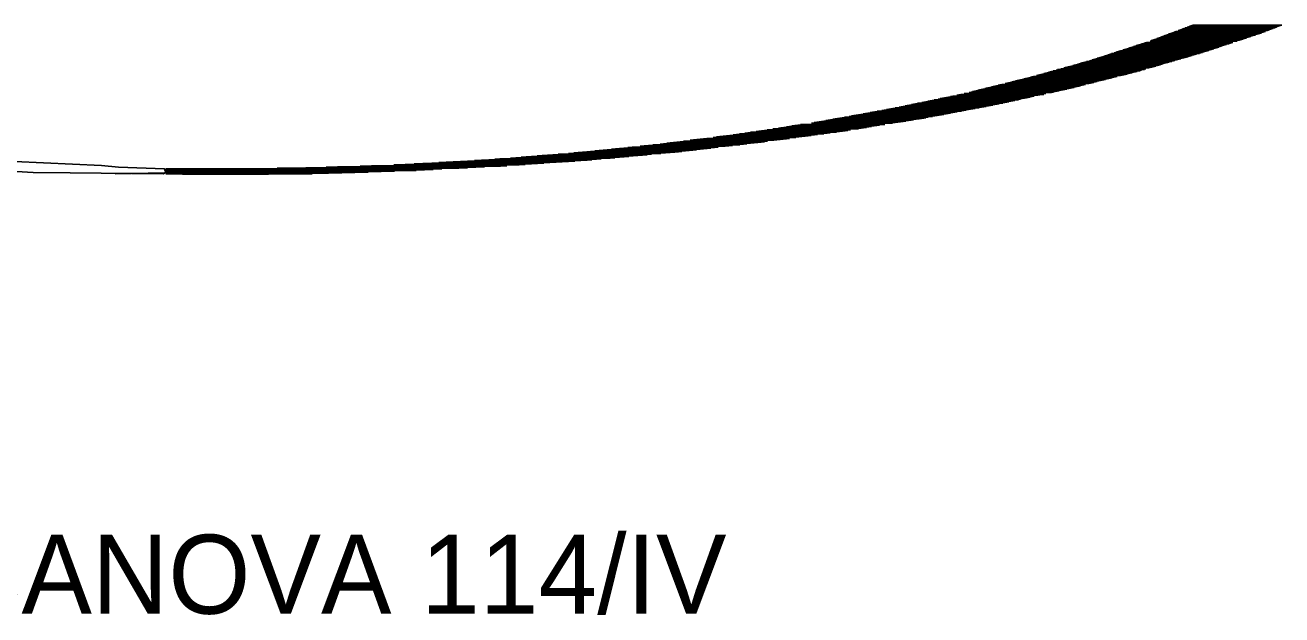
# Model space of a CAD drawing. Extents: x -5481 to -5365, y -3322 to -3178.
# Drawn here: x -5369.567 to -5367.183, y -3315.957 to -3314.837 of the extents above; entities that cross this region are included whole.
import ezdxf

# ---------------------------------------------------------------- set-up
doc = ezdxf.new("R2010")
doc.units = 0
doc.layers.add('Nová vrstva (0)', color=7, linetype='Continuous')

msp = doc.modelspace()

# ---------------------------------------------------------------- linework, layer by layer
at = {"layer": 'Nová vrstva (0)'}
for p, q in [((-5367.3853, -3314.8501), (-5367.2158, -3314.8501)), ((-5367.3834, -3314.8493), (-5367.2138, -3314.8493)), ((-5367.3792, -3314.8479), (-5367.2095, -3314.8479)), ((-5367.377, -3314.8468), (-5367.2079, -3314.8468)), ((-5367.375, -3314.8464), (-5367.2057, -3314.8464)), ((-5367.3726, -3314.8454), (-5367.2035, -3314.8454)), ((-5367.3706, -3314.8446), (-5367.2016, -3314.8446)), ((-5367.3685, -3314.844), (-5367.1992, -3314.844)), ((-5367.3662, -3314.8427), (-5367.1971, -3314.8427)), ((-5367.3642, -3314.8423), (-5367.195, -3314.8423)), ((-5367.3619, -3314.8412), (-5367.193, -3314.8412)), ((-5367.3599, -3314.8407), (-5367.1912, -3314.8407)), ((-5367.3578, -3314.8396), (-5367.189, -3314.8396)), ((-5367.3555, -3314.8388), (-5367.187, -3314.8388)), ((-5367.3535, -3314.8381), (-5367.1848, -3314.8381)), ((-5367.3512, -3314.8374), (-5367.1825, -3314.8374)), ((-5367.4491, -3314.8732), (-5367.2851, -3314.8732)), ((-5367.4467, -3314.8728), (-5367.2825, -3314.8728)), ((-5367.4444, -3314.8718), (-5367.2802, -3314.8718)), ((-5367.4419, -3314.8709), (-5367.2779, -3314.8709)), ((-5367.4395, -3314.8703), (-5367.2754, -3314.8703)), ((-5367.4326, -3314.8679), (-5367.2682, -3314.8679)), ((-5367.4304, -3314.8668), (-5367.2658, -3314.8668)), ((-5367.4282, -3314.8662), (-5367.2632, -3314.8662)), ((-5367.4262, -3314.8651), (-5367.2609, -3314.8651)), ((-5367.4241, -3314.8645), (-5367.2584, -3314.8645)), ((-5367.4219, -3314.864), (-5367.2561, -3314.864)), ((-5367.4198, -3314.8629), (-5367.2537, -3314.8629)), ((-5367.4176, -3314.862), (-5367.2511, -3314.862)), ((-5367.4154, -3314.8615), (-5367.2487, -3314.8615)), ((-5367.4131, -3314.8603), (-5367.2462, -3314.8603)), ((-5367.4111, -3314.8598), (-5367.2439, -3314.8598)), ((-5367.4089, -3314.8588), (-5367.2416, -3314.8588)), ((-5367.4067, -3314.8579), (-5367.239, -3314.8579)), ((-5367.4046, -3314.8574), (-5367.2367, -3314.8574)), ((-5367.4023, -3314.8564), (-5367.2341, -3314.8564)), ((-5367.4004, -3314.8557), (-5367.2317, -3314.8557)), ((-5367.3982, -3314.8549), (-5367.2293, -3314.8549)), ((-5367.3962, -3314.8542), (-5367.2269, -3314.8542)), ((-5367.3941, -3314.8535), (-5367.2246, -3314.8535)), ((-5367.3918, -3314.8525), (-5367.2223, -3314.8525)), ((-5367.3899, -3314.8518), (-5367.2203, -3314.8518)), ((-5367.3877, -3314.851), (-5367.2181, -3314.851)), ((-5367.5228, -3314.8975), (-5367.3606, -3314.8975)), ((-5367.5205, -3314.8965), (-5367.358, -3314.8965)), ((-5367.5176, -3314.8957), (-5367.3551, -3314.8957)), ((-5367.5153, -3314.895), (-5367.3525, -3314.895)), ((-5367.5129, -3314.894), (-5367.3496, -3314.894)), ((-5367.5105, -3314.8933), (-5367.347, -3314.8933)), ((-5367.5082, -3314.8926), (-5367.3443, -3314.8926)), ((-5367.5057, -3314.8915), (-5367.3416, -3314.8915)), ((-5367.5031, -3314.8911), (-5367.3386, -3314.8911)), ((-5367.5006, -3314.8898), (-5367.336, -3314.8898)), ((-5367.4983, -3314.8896), (-5367.3333, -3314.8896)), ((-5367.496, -3314.8884), (-5367.3308, -3314.8884)), ((-5367.4933, -3314.8876), (-5367.3284, -3314.8876)), ((-5367.491, -3314.887), (-5367.3261, -3314.887)), ((-5367.4887, -3314.8859), (-5367.3237, -3314.8859)), ((-5367.4858, -3314.8854), (-5367.3213, -3314.8854)), ((-5367.4834, -3314.8845), (-5367.3188, -3314.8845)), ((-5367.4812, -3314.8835), (-5367.3163, -3314.8835)), ((-5367.4786, -3314.8831), (-5367.3139, -3314.8831)), ((-5367.4763, -3314.8823), (-5367.3114, -3314.8823)), ((-5367.4738, -3314.8811), (-5367.3091, -3314.8811)), ((-5367.4715, -3314.8806), (-5367.3068, -3314.8806)), ((-5367.4689, -3314.8796), (-5367.3043, -3314.8796)), ((-5367.4664, -3314.8792), (-5367.3021, -3314.8792)), ((-5367.4641, -3314.8781), (-5367.2994, -3314.8781)), ((-5367.4615, -3314.8771), (-5367.2969, -3314.8771)), ((-5367.4591, -3314.8764), (-5367.2946, -3314.8764)), ((-5367.4567, -3314.8757), (-5367.2924, -3314.8757)), ((-5367.4541, -3314.8748), (-5367.2899, -3314.8748)), ((-5367.4516, -3314.8742), (-5367.2876, -3314.8742)), ((-5367.6053, -3314.9214), (-5367.4434, -3314.9214)), ((-5367.6021, -3314.9204), (-5367.4407, -3314.9204)), ((-5367.5963, -3314.9187), (-5367.4349, -3314.9187)), ((-5367.5936, -3314.9179), (-5367.4322, -3314.9179)), ((-5367.5907, -3314.9172), (-5367.4295, -3314.9172)), ((-5367.5879, -3314.9165), (-5367.4267, -3314.9165)), ((-5367.5847, -3314.9158), (-5367.4241, -3314.9158)), ((-5367.582, -3314.915), (-5367.4214, -3314.915)), ((-5367.5791, -3314.9139), (-5367.4185, -3314.9139)), ((-5367.5764, -3314.9131), (-5367.4157, -3314.9131)), ((-5367.5736, -3314.9126), (-5367.4131, -3314.9126)), ((-5367.5704, -3314.9117), (-5367.4104, -3314.9117)), ((-5367.5674, -3314.9109), (-5367.4075, -3314.9109)), ((-5367.5647, -3314.9098), (-5367.405, -3314.9098)), ((-5367.5618, -3314.9092), (-5367.4019, -3314.9092)), ((-5367.559, -3314.9084), (-5367.3992, -3314.9084)), ((-5367.5562, -3314.9078), (-5367.3964, -3314.9078)), ((-5367.5531, -3314.9067), (-5367.3937, -3314.9067)), ((-5367.5504, -3314.9062), (-5367.391, -3314.9062)), ((-5367.5475, -3314.905), (-5367.3883, -3314.905)), ((-5367.5448, -3314.9048), (-5367.3853, -3314.9048)), ((-5367.5424, -3314.9036), (-5367.3827, -3314.9036)), ((-5367.54, -3314.9028), (-5367.38, -3314.9028)), ((-5367.5375, -3314.902), (-5367.3774, -3314.902)), ((-5367.5351, -3314.9011), (-5367.3745, -3314.9011)), ((-5367.5327, -3314.9004), (-5367.372, -3314.9004)), ((-5367.5301, -3314.8996), (-5367.3688, -3314.8996)), ((-5367.5278, -3314.8989), (-5367.366, -3314.8989)), ((-5367.5252, -3314.8981), (-5367.3633, -3314.8981)), ((-5367.6947, -3314.9453), (-5367.536, -3314.9453)), ((-5367.6917, -3314.9444), (-5367.5328, -3314.9444)), ((-5367.6881, -3314.9433), (-5367.5299, -3314.9433)), ((-5367.6849, -3314.9428), (-5367.5267, -3314.9428)), ((-5367.6816, -3314.9419), (-5367.5236, -3314.9419)), ((-5367.6784, -3314.9411), (-5367.5205, -3314.9411)), ((-5367.6753, -3314.9404), (-5367.5172, -3314.9404)), ((-5367.6721, -3314.9394), (-5367.5142, -3314.9394)), ((-5367.6688, -3314.9387), (-5367.511, -3314.9387)), ((-5367.6655, -3314.938), (-5367.5079, -3314.938)), ((-5367.6628, -3314.9372), (-5367.5048, -3314.9372)), ((-5367.6598, -3314.9365), (-5367.5013, -3314.9365)), ((-5367.6572, -3314.9358), (-5367.4983, -3314.9358)), ((-5367.654, -3314.9348), (-5367.4951, -3314.9348)), ((-5367.6481, -3314.9333), (-5367.4889, -3314.9333)), ((-5367.6454, -3314.9322), (-5367.4856, -3314.9322)), ((-5367.6425, -3314.9317), (-5367.4825, -3314.9317)), ((-5367.6398, -3314.9309), (-5367.4795, -3314.9309)), ((-5367.6368, -3314.9302), (-5367.4763, -3314.9302)), ((-5367.6339, -3314.9292), (-5367.4733, -3314.9292)), ((-5367.631, -3314.9284), (-5367.4701, -3314.9284)), ((-5367.6281, -3314.9278), (-5367.4667, -3314.9278)), ((-5367.6252, -3314.9267), (-5367.4638, -3314.9267)), ((-5367.6224, -3314.9258), (-5367.4604, -3314.9258)), ((-5367.6194, -3314.9253), (-5367.4574, -3314.9253)), ((-5367.6166, -3314.9243), (-5367.4544, -3314.9243)), ((-5367.6136, -3314.9239), (-5367.4516, -3314.9239)), ((-5367.6109, -3314.9228), (-5367.4489, -3314.9228)), ((-5367.6081, -3314.9219), (-5367.446, -3314.9219)), ((-5367.7919, -3314.9692), (-5367.6383, -3314.9692)), ((-5367.7887, -3314.9688), (-5367.6344, -3314.9688)), ((-5367.7853, -3314.9675), (-5367.6307, -3314.9675)), ((-5367.7756, -3314.965), (-5367.6196, -3314.965)), ((-5367.7724, -3314.9644), (-5367.6159, -3314.9644)), ((-5367.7693, -3314.9636), (-5367.6124, -3314.9636)), ((-5367.7659, -3314.9627), (-5367.6088, -3314.9627)), ((-5367.7627, -3314.9622), (-5367.6053, -3314.9622)), ((-5367.7596, -3314.9611), (-5367.6014, -3314.9611)), ((-5367.7562, -3314.9602), (-5367.5977, -3314.9602)), ((-5367.7528, -3314.9595), (-5367.5943, -3314.9595)), ((-5367.7497, -3314.9588), (-5367.5906, -3314.9588)), ((-5367.7464, -3314.9578), (-5367.5869, -3314.9578)), ((-5367.7434, -3314.957), (-5367.5833, -3314.957)), ((-5367.7402, -3314.9563), (-5367.5802, -3314.9563)), ((-5367.7368, -3314.9556), (-5367.5769, -3314.9556)), ((-5367.7335, -3314.9548), (-5367.5739, -3314.9548)), ((-5367.7303, -3314.9539), (-5367.5708, -3314.9539)), ((-5367.7271, -3314.9533), (-5367.5674, -3314.9533)), ((-5367.7239, -3314.9524), (-5367.5644, -3314.9524)), ((-5367.7207, -3314.9514), (-5367.5612, -3314.9514)), ((-5367.7174, -3314.9506), (-5367.5582, -3314.9506)), ((-5367.714, -3314.95), (-5367.5552, -3314.95)), ((-5367.7077, -3314.9485), (-5367.5487, -3314.9485)), ((-5367.7041, -3314.9475), (-5367.5457, -3314.9475)), ((-5367.701, -3314.9467), (-5367.5424, -3314.9467)), ((-5367.6978, -3314.9463), (-5367.5393, -3314.9463)), ((-5367.9089, -3314.993), (-5367.7523, -3314.993)), ((-5367.9047, -3314.9922), (-5367.7481, -3314.9922)), ((-5367.9011, -3314.9917), (-5367.7437, -3314.9917)), ((-5367.8972, -3314.9905), (-5367.7395, -3314.9905)), ((-5367.8934, -3314.9897), (-5367.7352, -3314.9897)), ((-5367.8893, -3314.9891), (-5367.731, -3314.9891)), ((-5367.8853, -3314.9883), (-5367.7269, -3314.9883)), ((-5367.8815, -3314.9875), (-5367.7227, -3314.9875)), ((-5367.8775, -3314.9869), (-5367.7188, -3314.9869)), ((-5367.8739, -3314.9858), (-5367.7152, -3314.9858)), ((-5367.8695, -3314.9853), (-5367.7117, -3314.9853)), ((-5367.8656, -3314.9841), (-5367.708, -3314.9841)), ((-5367.8618, -3314.9834), (-5367.7041, -3314.9834)), ((-5367.8582, -3314.9827), (-5367.7005, -3314.9827)), ((-5367.8542, -3314.9819), (-5367.6969, -3314.9819)), ((-5367.8502, -3314.9811), (-5367.6931, -3314.9811)), ((-5367.8464, -3314.9805), (-5367.6895, -3314.9805)), ((-5367.8424, -3314.9795), (-5367.6857, -3314.9795)), ((-5367.8383, -3314.9791), (-5367.6822, -3314.9791)), ((-5367.8346, -3314.9778), (-5367.6784, -3314.9778)), ((-5367.8307, -3314.9769), (-5367.675, -3314.9769)), ((-5367.8268, -3314.9763), (-5367.6711, -3314.9763)), ((-5367.8228, -3314.9753), (-5367.6674, -3314.9753)), ((-5367.819, -3314.9749), (-5367.6638, -3314.9749)), ((-5367.815, -3314.9739), (-5367.6601, -3314.9739)), ((-5367.8112, -3314.9731), (-5367.6564, -3314.9731)), ((-5367.8071, -3314.9724), (-5367.6527, -3314.9724)), ((-5367.7994, -3314.9705), (-5367.6454, -3314.9705)), ((-5367.7956, -3314.97), (-5367.642, -3314.97)), ((-5368.0344, -3315.0161), (-5367.8764, -3315.0161)), ((-5368.03, -3315.0154), (-5367.871, -3315.0154)), ((-5368.0256, -3315.0149), (-5367.8663, -3315.0149)), ((-5368.021, -3315.0139), (-5367.8621, -3315.0139)), ((-5368.0167, -3315.0135), (-5367.8579, -3315.0135)), ((-5368.0122, -3315.0122), (-5367.8534, -3315.0122)), ((-5368.0033, -3315.0108), (-5367.8452, -3315.0108)), ((-5367.9991, -3315.0097), (-5367.8408, -3315.0097)), ((-5367.9946, -3315.0091), (-5367.8365, -3315.0091)), ((-5367.9902, -3315.0083), (-5367.8325, -3315.0083)), ((-5367.9858, -3315.0074), (-5367.8283, -3315.0074)), ((-5367.9813, -3315.0069), (-5367.8241, -3315.0069)), ((-5367.977, -3315.0058), (-5367.8198, -3315.0058)), ((-5367.9724, -3315.0049), (-5367.8157, -3315.0049)), ((-5367.9681, -3315.0044), (-5367.8115, -3315.0044)), ((-5367.9637, -3315.0035), (-5367.8071, -3315.0035)), ((-5367.9595, -3315.0024), (-5367.8028, -3315.0024)), ((-5367.9548, -3315.0019), (-5367.7987, -3315.0019)), ((-5367.9504, -3315.001), (-5367.7945, -3315.001)), ((-5367.9462, -3315.0005), (-5367.7902, -3315.0005)), ((-5367.9416, -3314.9996), (-5367.7858, -3314.9996)), ((-5367.9372, -3314.9985), (-5367.7816, -3314.9985)), ((-5367.9328, -3314.9978), (-5367.7774, -3314.9978)), ((-5367.9284, -3314.9971), (-5367.7734, -3314.9971)), ((-5367.9246, -3314.9961), (-5367.7691, -3314.9961)), ((-5367.9206, -3314.9956), (-5367.7648, -3314.9956)), ((-5367.9166, -3314.9947), (-5367.7607, -3314.9947)), ((-5367.9127, -3314.9941), (-5367.7566, -3314.9941)), ((-5368.1909, -3315.0408), (-5368.0337, -3315.0408)), ((-5368.1854, -3315.0404), (-5368.0277, -3315.0404)), ((-5368.1802, -3315.0393), (-5368.0219, -3315.0393)), ((-5368.175, -3315.0388), (-5368.0161, -3315.0388)), ((-5368.1697, -3315.0379), (-5368.011, -3315.0379)), ((-5368.1645, -3315.0371), (-5368.006, -3315.0371)), ((-5368.1592, -3315.0363), (-5368.001, -3315.0363)), ((-5368.1487, -3315.0344), (-5367.9908, -3315.0344)), ((-5368.1435, -3315.034), (-5367.986, -3315.034)), ((-5368.138, -3315.033), (-5367.981, -3315.033)), ((-5368.133, -3315.0325), (-5367.9761, -3315.0325)), ((-5368.1277, -3315.0315), (-5367.971, -3315.0315)), ((-5368.1223, -3315.0305), (-5367.9662, -3315.0305)), ((-5368.1171, -3315.0301), (-5367.9613, -3315.0301)), ((-5368.1121, -3315.0288), (-5367.956, -3315.0288)), ((-5368.1065, -3315.0282), (-5367.9511, -3315.0282)), ((-5368.1013, -3315.0274), (-5367.9462, -3315.0274)), ((-5368.096, -3315.0263), (-5367.9412, -3315.0263)), ((-5368.0908, -3315.026), (-5367.9361, -3315.026)), ((-5368.0749, -3315.0235), (-5367.9211, -3315.0235)), ((-5368.0698, -3315.0224), (-5367.9161, -3315.0224)), ((-5368.0652, -3315.0218), (-5367.9113, -3315.0218)), ((-5368.0607, -3315.021), (-5367.9061, -3315.021)), ((-5368.0564, -3315.0202), (-5367.9011, -3315.0202)), ((-5368.0519, -3315.0196), (-5367.8962, -3315.0196)), ((-5368.0476, -3315.0186), (-5367.8912, -3315.0186)), ((-5368.0432, -3315.0179), (-5367.8862, -3315.0179)), ((-5368.0387, -3315.0171), (-5367.8813, -3315.0171)), ((-5368.3686, -3315.0645), (-5368.2112, -3315.0645)), ((-5368.3623, -3315.0632), (-5368.2042, -3315.0632)), ((-5368.3559, -3315.0626), (-5368.1975, -3315.0626)), ((-5368.3496, -3315.0615), (-5368.1906, -3315.0615)), ((-5368.3433, -3315.0608), (-5368.1839, -3315.0608)), ((-5368.337, -3315.0599), (-5368.177, -3315.0599)), ((-5368.3307, -3315.0596), (-5368.1705, -3315.0596)), ((-5368.3243, -3315.0587), (-5368.1645, -3315.0587)), ((-5368.318, -3315.0579), (-5368.1586, -3315.0579)), ((-5368.3055, -3315.056), (-5368.1468, -3315.056)), ((-5368.2991, -3315.0554), (-5368.1407, -3315.0554)), ((-5368.2928, -3315.0545), (-5368.1346, -3315.0545)), ((-5368.2866, -3315.0538), (-5368.129, -3315.0538)), ((-5368.2803, -3315.053), (-5368.1228, -3315.053)), ((-5368.2739, -3315.0523), (-5368.1168, -3315.0523)), ((-5368.2614, -3315.0508), (-5368.1049, -3315.0508)), ((-5368.2551, -3315.0496), (-5368.0992, -3315.0496)), ((-5368.2487, -3315.0491), (-5368.0932, -3315.0491)), ((-5368.2425, -3315.0482), (-5368.0872, -3315.0482)), ((-5368.2362, -3315.0474), (-5368.0814, -3315.0474)), ((-5368.2301, -3315.0466), (-5368.0754, -3315.0466)), ((-5368.2236, -3315.0457), (-5368.0693, -3315.0457)), ((-5368.2172, -3315.0452), (-5368.0635, -3315.0452)), ((-5368.2118, -3315.044), (-5368.0574, -3315.044)), ((-5368.2066, -3315.0435), (-5368.0514, -3315.0435)), ((-5368.2014, -3315.0425), (-5368.0456, -3315.0425)), ((-5368.1961, -3315.0418), (-5368.0395, -3315.0418)), ((-5368.626, -3315.0882), (-5368.4396, -3315.0882)), ((-5368.6162, -3315.0873), (-5368.4308, -3315.0873)), ((-5368.6062, -3315.0867), (-5368.422, -3315.0867)), ((-5368.5959, -3315.0854), (-5368.4133, -3315.0854)), ((-5368.5861, -3315.0851), (-5368.4044, -3315.0851)), ((-5368.5761, -3315.084), (-5368.3955, -3315.084)), ((-5368.5661, -3315.0835), (-5368.3869, -3315.0835)), ((-5368.5561, -3315.0826), (-5368.3784, -3315.0826)), ((-5368.5361, -3315.0812), (-5368.3607, -3315.0812)), ((-5368.5259, -3315.0801), (-5368.3519, -3315.0801)), ((-5368.5176, -3315.0792), (-5368.3431, -3315.0792)), ((-5368.5095, -3315.0784), (-5368.3347, -3315.0784)), ((-5368.5017, -3315.0777), (-5368.3277, -3315.0777)), ((-5368.4943, -3315.077), (-5368.321, -3315.077)), ((-5368.4861, -3315.0762), (-5368.314, -3315.0762)), ((-5368.4783, -3315.0751), (-5368.3072, -3315.0751)), ((-5368.4705, -3315.0748), (-5368.3003, -3315.0748)), ((-5368.4626, -3315.0738), (-5368.2933, -3315.0738)), ((-5368.4548, -3315.0728), (-5368.2866, -3315.0728)), ((-5368.4471, -3315.0721), (-5368.2798, -3315.0721)), ((-5368.4393, -3315.0713), (-5368.2728, -3315.0713)), ((-5368.4314, -3315.0709), (-5368.2661, -3315.0709)), ((-5368.4234, -3315.0699), (-5368.2589, -3315.0699)), ((-5368.4156, -3315.069), (-5368.2524, -3315.069)), ((-5368.4001, -3315.0674), (-5368.2386, -3315.0674)), ((-5368.3923, -3315.0665), (-5368.2317, -3315.0665)), ((-5368.3845, -3315.066), (-5368.2247, -3315.066)), ((-5368.3764, -3315.0649), (-5368.2182, -3315.0649)), ((-5369.3, -3315.1104), (-5368.7765, -3315.1104)), ((-5369.3, -3315.1112), (-5368.7932, -3315.1112)), ((-5369.3, -3315.1118), (-5368.8094, -3315.1118)), ((-5369.0893, -3315.109), (-5368.7443, -3315.109)), ((-5369.0344, -3315.1082), (-5368.7279, -3315.1082)), ((-5368.9962, -3315.1073), (-5368.7119, -3315.1073)), ((-5368.9748, -3315.1065), (-5368.6958, -3315.1065)), ((-5368.9318, -3315.1048), (-5368.6654, -3315.1048)), ((-5368.9103, -3315.1043), (-5368.6533, -3315.1043)), ((-5368.8676, -3315.1026), (-5368.63, -3315.1026)), ((-5368.8461, -3315.1017), (-5368.6183, -3315.1017)), ((-5368.829, -3315.1009), (-5368.6065, -3315.1009)), ((-5368.8126, -3315.1001), (-5368.5948, -3315.1001)), ((-5368.7958, -3315.0995), (-5368.5831, -3315.0995)), ((-5368.7821, -3315.0984), (-5368.5713, -3315.0984)), ((-5368.7685, -3315.0977), (-5368.5596, -3315.0977)), ((-5368.7551, -3315.097), (-5368.5479, -3315.097)), ((-5368.7413, -3315.0962), (-5368.5361, -3315.0962)), ((-5368.7279, -3315.0953), (-5368.5242, -3315.0953)), ((-5368.7144, -3315.0943), (-5368.5126, -3315.0943)), ((-5368.7011, -3315.0938), (-5368.5008, -3315.0938)), ((-5368.6873, -3315.0929), (-5368.492, -3315.0929)), ((-5368.6762, -3315.0921), (-5368.4833, -3315.0921)), ((-5368.6662, -3315.0914), (-5368.4744, -3315.0914)), ((-5368.646, -3315.0899), (-5368.457, -3315.0899)), ((-5368.6362, -3315.089), (-5368.4484, -3315.089)), ((-5369.3963, -3315.1195), (-5369.3027, -3315.1178)), ((-5369.3003, -3315.1178), (-5368.9666, -3315.1178)), ((-5369.3003, -3315.1184), (-5368.9917, -3315.1184)), ((-5369.3003, -3315.1195), (-5369.0225, -3315.1195)), ((-5369.3, -3315.1131), (-5368.8254, -3315.1131)), ((-5369.3, -3315.1134), (-5368.8414, -3315.1134)), ((-5369.3, -3315.1148), (-5368.8664, -3315.1148)), ((-5369.3, -3315.1153), (-5368.8916, -3315.1153)), ((-5369.3, -3315.1162), (-5368.9164, -3315.1162)), ((-5369.3, -3315.117), (-5368.9415, -3315.117)), ((-5369.2685, -3315.12), (-5369.1057, -3315.12))]:
    msp.add_line(p, q, dxfattribs=at)
msp.add_lwpolyline([(-5369.7634, -3315.1043), (-5369.5523, -3315.1173), (-5369.4815, -3315.1178), (-5369.3052, -3315.1195), (-5369.3005, -3315.1173), (-5369.3027, -3315.1104), (-5369.39, -3315.1068), (-5369.4225, -3315.104), (-5369.5875, -3315.0962)], dxfattribs=at)

# ---------------------------------------------------------------- texts
msp.add_text(' ROKYCANOVA 114/IV', height=0.15, dxfattribs=at).set_placement((-5370.3433, -3315.9545))

doc.saveas('drawing.dxf')
